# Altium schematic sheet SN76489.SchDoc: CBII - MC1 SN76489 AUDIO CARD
size A2; Engineer: SRKH; DocumentNumber: 1; Revision: 1.02; SheetNumber: 1; SheetTotal: 1
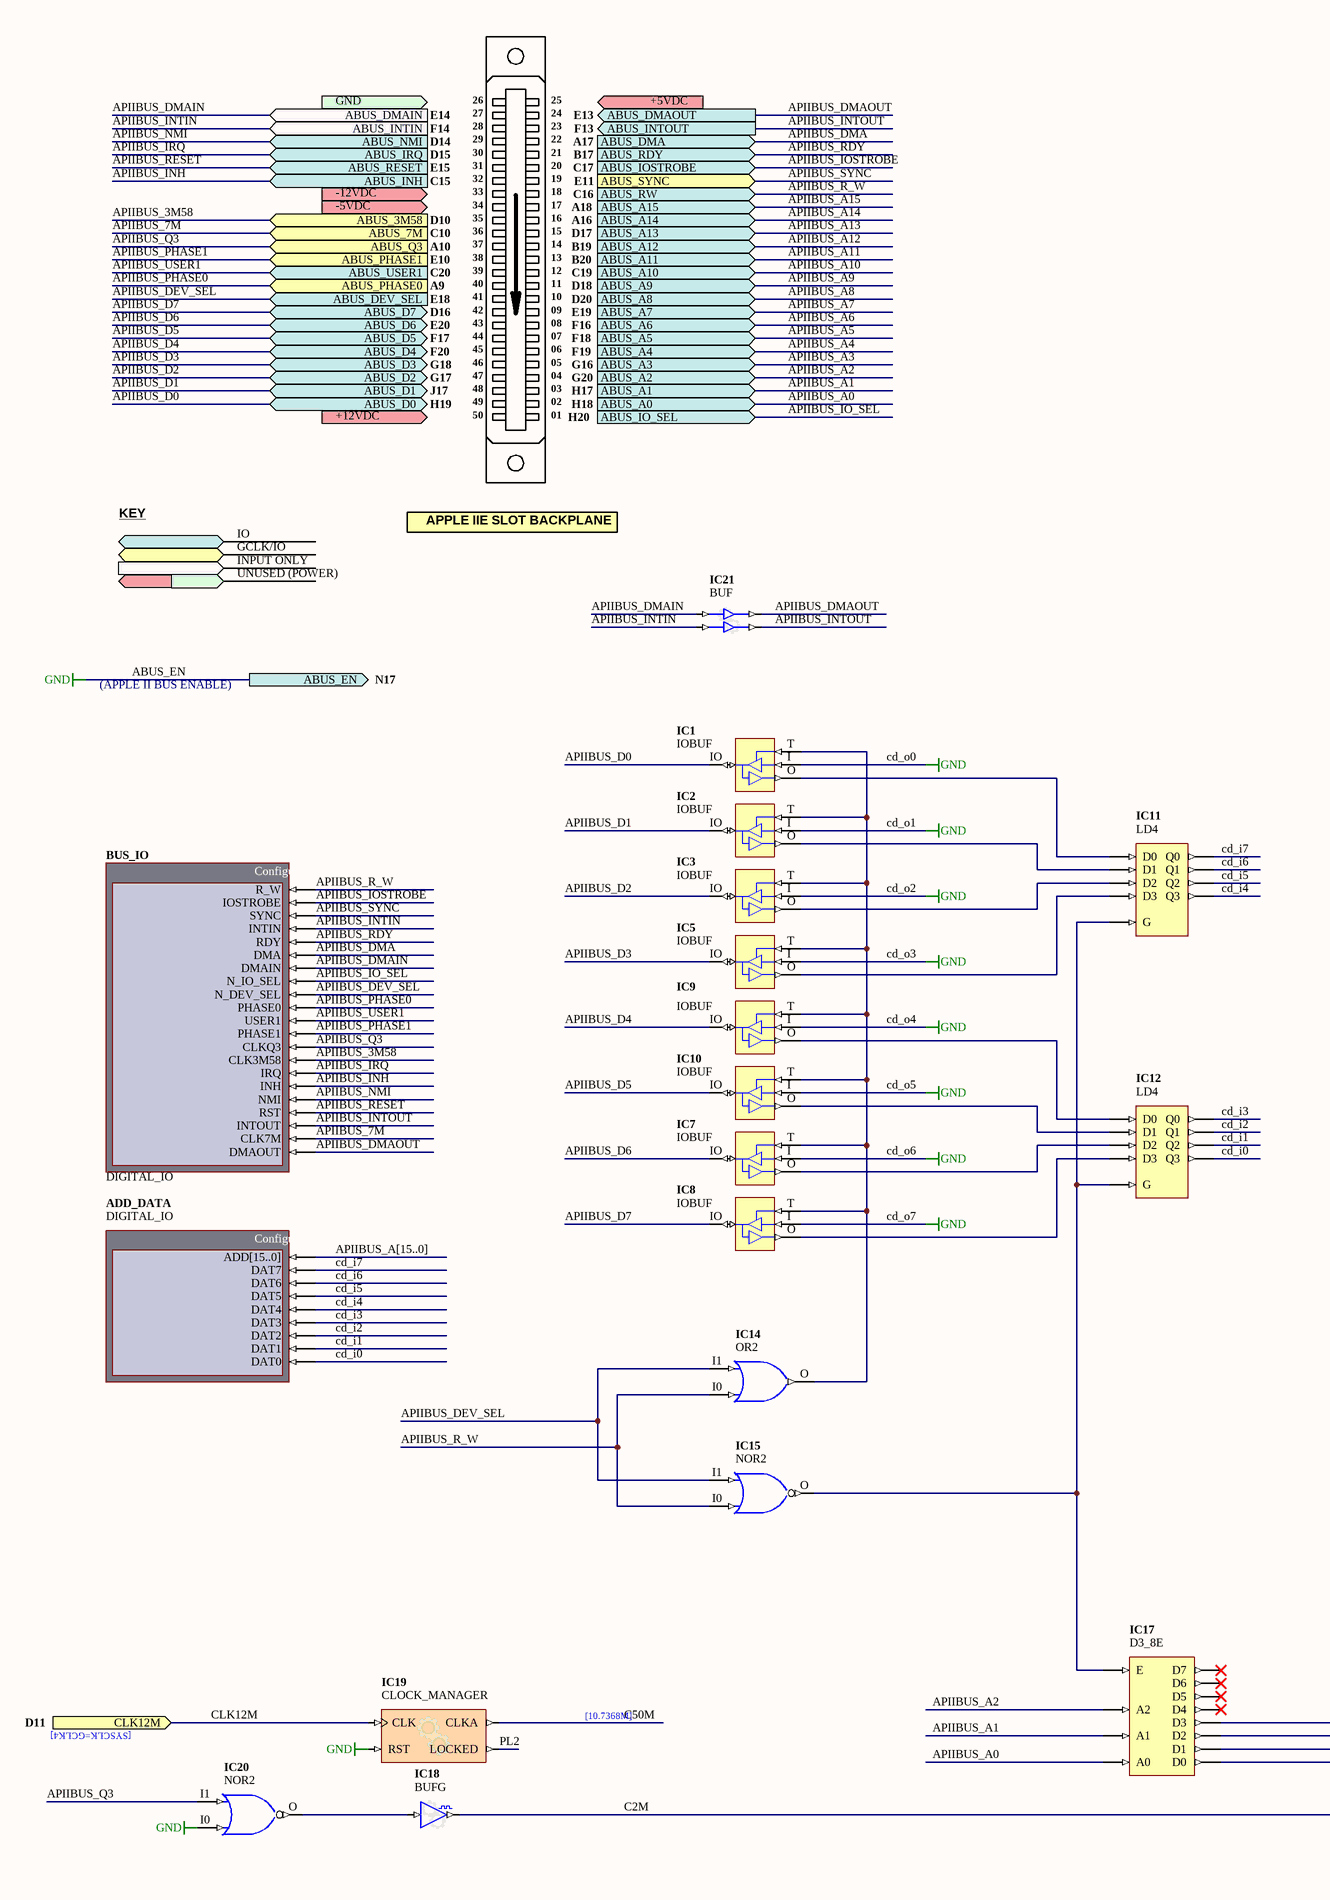
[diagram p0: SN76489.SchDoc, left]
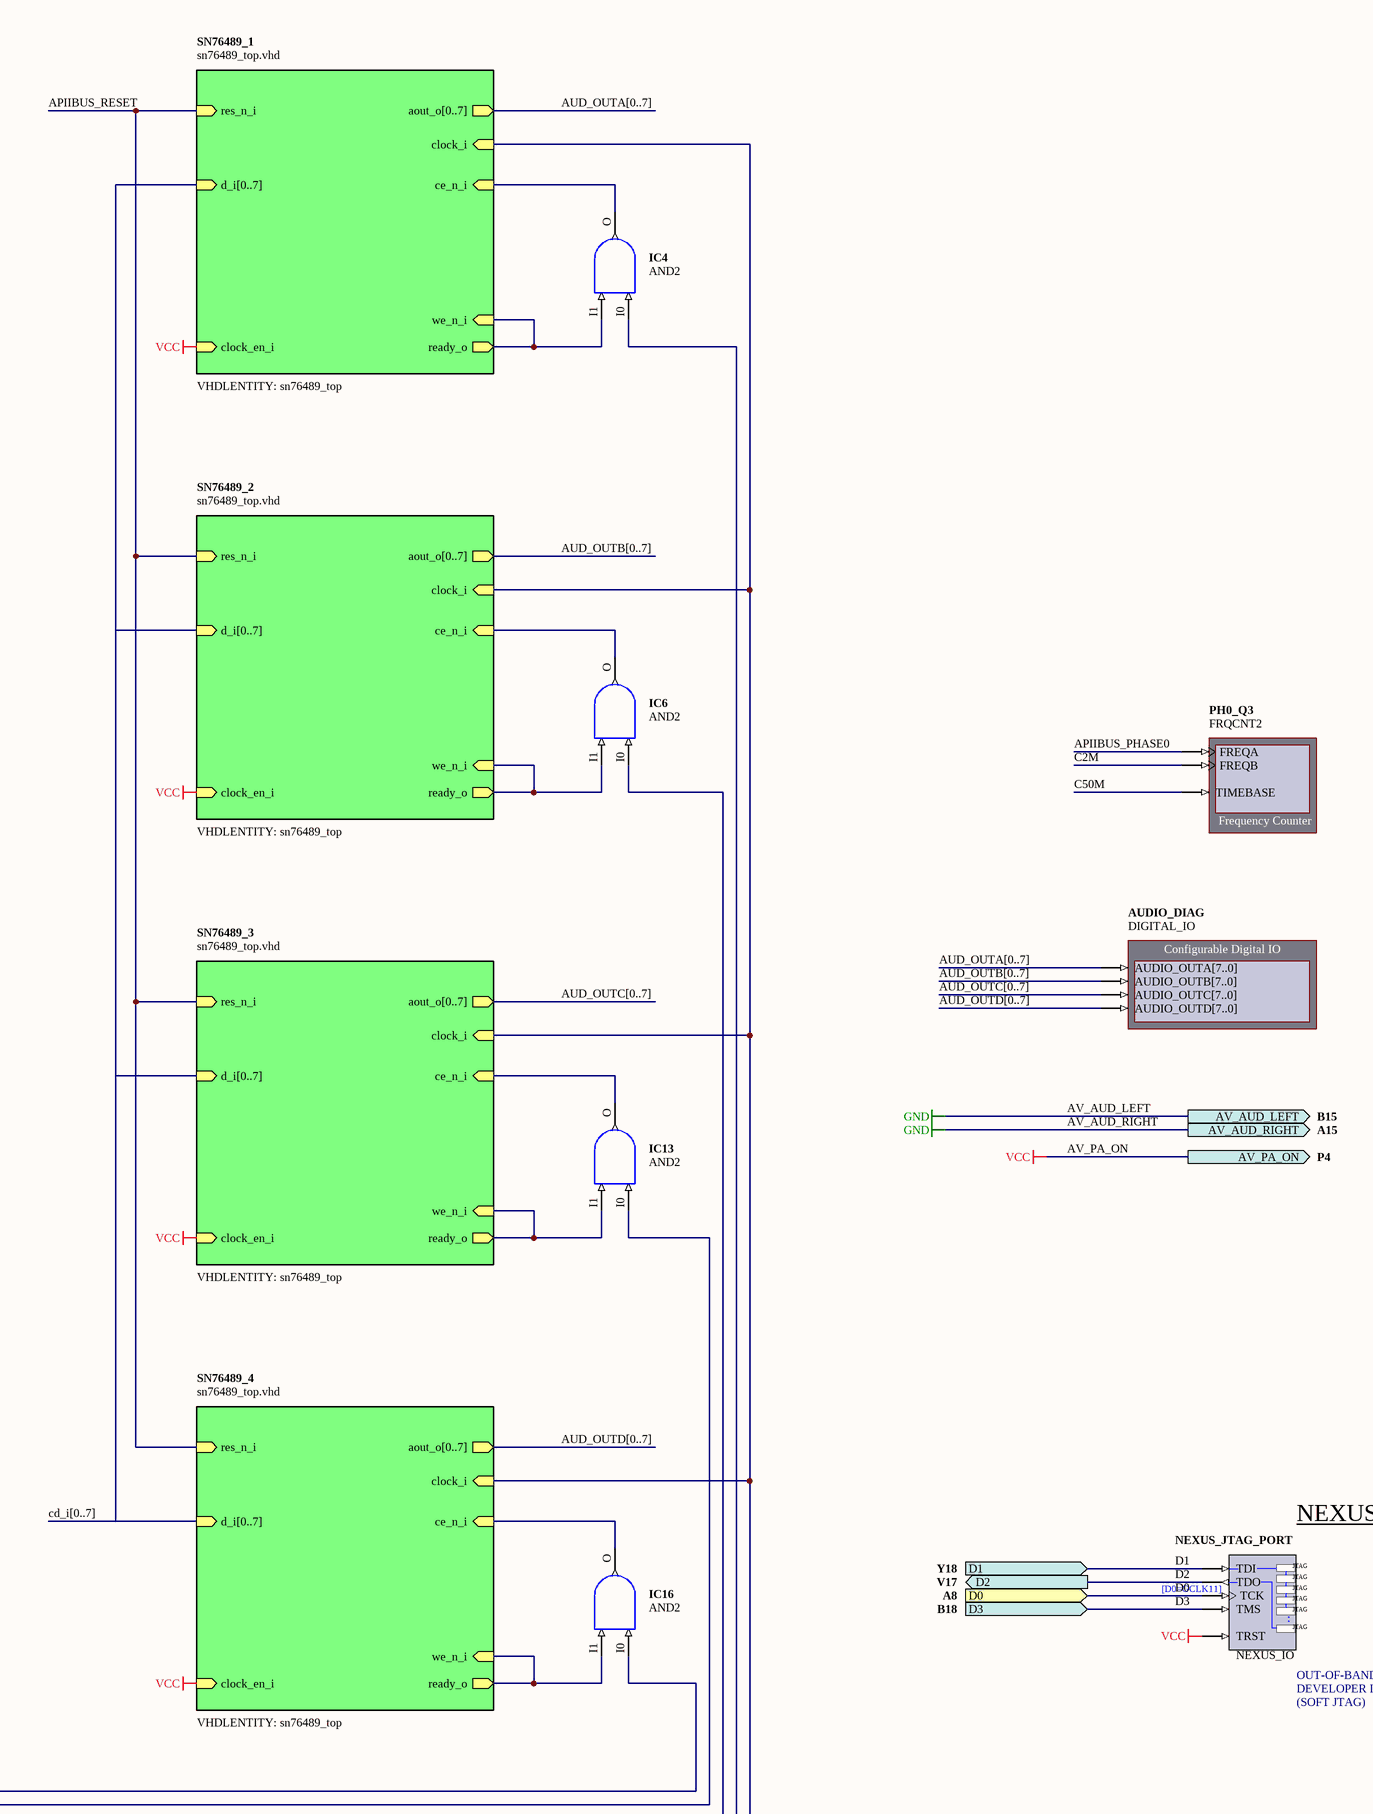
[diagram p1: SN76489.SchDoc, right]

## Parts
ADD_DATA  DIGITAL_IO
AUDIO_DIAG  DIGITAL_IO
BUS_IO  DIGITAL_IO
IC1  IOBUF
IC2  IOBUF
IC3  IOBUF
IC4  AND2
IC5  IOBUF
IC6  AND2
IC7  IOBUF
IC8  IOBUF
IC9  IOBUF
IC10  IOBUF
IC11  LD4
IC12  LD4
IC13  AND2
IC14  OR2
IC15  NOR2
IC16  AND2
IC17  D3_8E
IC18  BUFG
IC19  CLOCK_MANAGER
IC20  NOR2
IC21  BUF
NEXUS_JTAG_PORT  NEXUS_IO
PH0_Q3  FRQCNT2

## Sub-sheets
SN76489_1 = sn76489_top.vhd: ce_n_i (in), clock_en_i (in), clock_i (in), d_i[0..7] (in), ready_o (out), res_n_i (in), we_n_i (in), aout_o[0..7] (out)  | VHDLENTITY: sn76489_top
SN76489_2 = sn76489_top.vhd: ce_n_i (in), clock_en_i (in), clock_i (in), d_i[0..7] (in), ready_o (out), res_n_i (in), we_n_i (in), aout_o[0..7] (out)  | VHDLENTITY: sn76489_top
SN76489_3 = sn76489_top.vhd: ce_n_i (in), clock_en_i (in), clock_i (in), d_i[0..7] (in), ready_o (out), res_n_i (in), we_n_i (in), aout_o[0..7] (out)  | VHDLENTITY: sn76489_top
SN76489_4 = sn76489_top.vhd: ce_n_i (in), clock_en_i (in), clock_i (in), d_i[0..7] (in), ready_o (out), res_n_i (in), we_n_i (in), aout_o[0..7] (out)  | VHDLENTITY: sn76489_top

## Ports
ABUS_3M58 (in, see D10), ABUS_7M (in, see C10), ABUS_A0 (in, see H18), ABUS_A1 (in, see H17), ABUS_A2 (in, see G20), ABUS_A3 (in, see G16), ABUS_A4 (in, see F19), ABUS_A5 (in, see F18), ABUS_A6 (in, see F16), ABUS_A7 (in, see E19), ABUS_A8 (in, see D20), ABUS_A9 (in, see D18), ABUS_A10 (in, see C19), ABUS_A11 (in, see B20), ABUS_A12 (in, see B19), ABUS_A13 (in, see D17), ABUS_A14 (in, see A16), ABUS_A15 (in, see A18), ABUS_D0 (bidir, see H19), ABUS_D1 (bidir, see J17), ABUS_D2 (bidir, see G17), ABUS_D3 (bidir, see G18), ABUS_D4 (bidir, see F20), ABUS_D5 (bidir, see F17), ABUS_D6 (bidir, see E20), ABUS_D7 (bidir, see D16), ABUS_DEV_SEL (in, see E18), ABUS_DMA (in, see A17), ABUS_DMAIN (in, see E14), ABUS_DMAOUT (out, see E13), ABUS_EN (out, see N17), ABUS_INH (in, see C15), ABUS_INTIN (in, see F14), ABUS_INTOUT (out, see F13), ABUS_IO_SEL (in, see H20), ABUS_IOSTROBE (in, see C17), ABUS_IRQ (in, see D15), ABUS_NMI (in, see D14), ABUS_PHASE0 (in, see A9), ABUS_PHASE1 (in, see E10), ABUS_Q3 (in, see A10), ABUS_RDY (in, see B17), ABUS_RESET (in, see E15), ABUS_RW (in, see C16), ABUS_SYNC (in, see E11), ABUS_USER1 (in, see C20), AV_AUD_LEFT (out, see B15), AV_AUD_RIGHT (out, see A15), AV_PA_ON (out, see P4), CLK12M (in, see D11), D0 (in, see A8), D1 (in, see Y18), D2 (out, see V17), D3 (in, see B18)

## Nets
ABUS_EN: IC1.I IC2.I IC3.I IC5.I IC7.I IC8.I IC9.I IC10.I IC19.RST IC20.I0 ; port ABUS_EN, port AV_AUD_LEFT, port AV_AUD_RIGHT  [also labelled AV_AUD_LEFT, AV_AUD_RIGHT, cd_o0, cd_o1, cd_o2, cd_o3, cd_o4, cd_o5, cd_o6, cd_o7, GND]
AV_PA_ON: NEXUS_JTAG_PORT.TRST ; port AV_PA_ON, sheet SN76489_1/clock_en_i, sheet SN76489_2/clock_en_i, sheet SN76489_3/clock_en_i, sheet SN76489_4/clock_en_i  [also labelled VCC]
APIIBUS_3M58: BUS_IO.CLK3M58 ; port ABUS_3M58
APIIBUS_7M: BUS_IO.CLK7M ; port ABUS_7M
APIIBUS_A0: IC17.A0 ; port ABUS_A0
APIIBUS_A1: IC17.A1 ; port ABUS_A1
APIIBUS_A2: IC17.A2 ; port ABUS_A2
APIIBUS_D0: IC1.IO ; port ABUS_D0
APIIBUS_D1: IC2.IO ; port ABUS_D1
APIIBUS_D2: IC3.IO ; port ABUS_D2
APIIBUS_D3: IC5.IO ; port ABUS_D3
APIIBUS_D4: IC9.IO ; port ABUS_D4
APIIBUS_D5: IC10.IO ; port ABUS_D5
APIIBUS_D6: IC7.IO ; port ABUS_D6
APIIBUS_D7: IC8.IO ; port ABUS_D7
APIIBUS_DEV_SEL: BUS_IO.N_DEV_SEL IC14.I1 IC15.I1 ; port ABUS_DEV_SEL
APIIBUS_DMA: BUS_IO.DMA ; port ABUS_DMA
APIIBUS_DMAIN: BUS_IO.DMAIN IC21.I0 ; port ABUS_DMAIN
APIIBUS_DMAOUT: BUS_IO.DMAOUT IC21.O0 ; port ABUS_DMAOUT
APIIBUS_INH: BUS_IO.INH ; port ABUS_INH
APIIBUS_INTIN: BUS_IO.INTIN IC21.I1 ; port ABUS_INTIN
APIIBUS_INTOUT: BUS_IO.INTOUT IC21.O1 ; port ABUS_INTOUT
APIIBUS_IO_SEL: BUS_IO.N_IO_SEL ; port ABUS_IO_SEL
APIIBUS_IOSTROBE: BUS_IO.IOSTROBE ; port ABUS_IOSTROBE
APIIBUS_IRQ: BUS_IO.IRQ ; port ABUS_IRQ
APIIBUS_NMI: BUS_IO.NMI ; port ABUS_NMI
APIIBUS_PHASE0: BUS_IO.PHASE0 PH0_Q3.FREQA ; port ABUS_PHASE0
APIIBUS_PHASE1: BUS_IO.PHASE1 ; port ABUS_PHASE1
APIIBUS_Q3: BUS_IO.CLKQ3 IC20.I1 ; port ABUS_Q3
APIIBUS_R_W: BUS_IO.R_W IC14.I0 IC15.I0 ; port ABUS_RW
APIIBUS_RDY: BUS_IO.RDY ; port ABUS_RDY
APIIBUS_RESET: BUS_IO.RST ; port ABUS_RESET, sheet SN76489_1/res_n_i, sheet SN76489_2/res_n_i, sheet SN76489_3/res_n_i, sheet SN76489_4/res_n_i
APIIBUS_SYNC: BUS_IO.SYNC ; port ABUS_SYNC
APIIBUS_USER1: BUS_IO.USER1 ; port ABUS_USER1
C2M: IC18.O PH0_Q3.FREQB ; sheet SN76489_1/clock_i, sheet SN76489_2/clock_i, sheet SN76489_3/clock_i, sheet SN76489_4/clock_i
C50M: IC19.CLKA PH0_Q3.TIMEBASE
cd_i0: ADD_DATA.DAT0 IC12.Q3
cd_i1: ADD_DATA.DAT1 IC12.Q2
cd_i2: ADD_DATA.DAT2 IC12.Q1
cd_i3: ADD_DATA.DAT3 IC12.Q0
cd_i4: ADD_DATA.DAT4 IC11.Q3
cd_i5: ADD_DATA.DAT5 IC11.Q2
cd_i6: ADD_DATA.DAT6 IC11.Q1
cd_i7: ADD_DATA.DAT7 IC11.Q0
CLK12M: IC19.CLK ; port CLK12M
D0: NEXUS_JTAG_PORT.TCK ; port D0
D1: NEXUS_JTAG_PORT.TDI ; port D1
D2: NEXUS_JTAG_PORT.TDO ; port D2
D3: NEXUS_JTAG_PORT.TMS ; port D3
PL2: IC19.LOCKED
NetIC1_O: IC1.O IC11.D0
NetIC1_T: IC1.T IC2.T IC3.T IC5.T IC7.T IC8.T IC9.T IC10.T IC14.O
NetIC2_O: IC2.O IC11.D1
NetIC3_O: IC3.O IC11.D2
NetIC4_I0: IC4.I0 IC17.D0
NetIC4_I1: IC4.I1 ; sheet SN76489_1/ready_o, sheet SN76489_1/we_n_i
NetIC4_O: IC4.O ; sheet SN76489_1/ce_n_i
NetIC5_O: IC5.O IC11.D3
NetIC6_I0: IC6.I0 IC17.D1
NetIC6_I1: IC6.I1 ; sheet SN76489_2/ready_o, sheet SN76489_2/we_n_i
NetIC6_O: IC6.O ; sheet SN76489_2/ce_n_i
NetIC7_O: IC7.O IC12.D2
NetIC8_O: IC8.O IC12.D3
NetIC9_O: IC9.O IC12.D0
NetIC10_O: IC10.O IC12.D1
NetIC11_G: IC11.G IC12.G IC15.O IC17.E
NetIC13_I0: IC13.I0 IC17.D2
NetIC13_I1: IC13.I1 ; sheet SN76489_3/ready_o, sheet SN76489_3/we_n_i
NetIC13_O: IC13.O ; sheet SN76489_3/ce_n_i
NetIC16_I0: IC16.I0 IC17.D3
NetIC16_I1: IC16.I1 ; sheet SN76489_4/ready_o, sheet SN76489_4/we_n_i
NetIC16_O: IC16.O ; sheet SN76489_4/ce_n_i
NetIC18_I: IC18.I IC20.O

Not connected (* = marked no-connect by the designer): ADD_DATA ADD[15..0]; AUDIO_DIAG AUDIO_OUTA[7..0] AUDIO_OUTB[7..0] AUDIO_OUTC[7..0] AUDIO_OUTD[7..0]; IC17 D4* D5* D6* D7*

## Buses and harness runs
bus APIIBUS_A[15..0]
bus AUD_OUTA[0..7]
bus AUD_OUTA[0..7] = sheet SN76489_1/aout_o[0..7]
bus AUD_OUTB[0..7]
bus AUD_OUTB[0..7] = sheet SN76489_2/aout_o[0..7]
bus AUD_OUTC[0..7]
bus AUD_OUTC[0..7] = sheet SN76489_3/aout_o[0..7]
bus AUD_OUTD[0..7]
bus AUD_OUTD[0..7] = sheet SN76489_4/aout_o[0..7]
bus cd_i[0..7] = sheet SN76489_1/d_i[0..7] = sheet SN76489_2/d_i[0..7] = sheet SN76489_3/d_i[0..7] = sheet SN76489_4/d_i[0..7]

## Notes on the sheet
- GND
- 26
- 27
- 25
- 24
- +5VDC
- 28
- 29
- 30
- 31
- 32
- 23
- 22
- 21
- 20
- 19
- -12VDC
- -5VDC
- 33
- 34
- 35
- 36
- 37
- 18
- 17
- 16
- 15
- 14
- 38
- 39
- 40
- 41
- 42
- 13
- 12
- 11
- 10
- 09
- 43
- 44
- 45
- 46
- 47
- 08
- 07
- 06
- 05
- 04
- +12VDC
- 48
- 49
- 50
- 03
- 02
- 01
- KEY
- IO
- GCLK/IO
- INPUT ONLY
- UNUSED (POWER)
- APPLE IIE SLOT BACKPLANE
- (APPLE II BUS ENABLE)
- (near NEXUS_JTAG_PORT) NEXUS
- [D0=GCLK11]
- (near NEXUS_JTAG_PORT) OUT-OF-BAND
- (near NEXUS_JTAG_PORT) DEVELOPER INTERFACE
- (SOFT JTAG)
- [SYSCLK=GCLK4]
- (near IC19) [10.7368M]

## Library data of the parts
ADD_DATA = DIGITAL_IO: Configurable Digital IO; NEXUS_CORE: Instrument; NEXUS_JTAG_DEVICE: True; NEXUS_JTAG_ORDER: 0; ConfigurationParameters: {}Version[2.0]{}StorageType[3]{}InterfaceType[Parallel]{}SchCompWidth[140]{}Input0Name[ADD{1}15..0{2}]{}Input0Width[16]{}Input0InitValue[0]{}Input0Kind[Numeric]{}Input0NumRadix[Decimal]{}Input1Name[DAT7]{}Input1Width[1]{}Input1InitValue[0]{}Input1Kind[Numeric]{}Input1NumRadix[Decimal]{}Input2Name[DAT6]{}Input2Width[1]{}Input2InitValue[0]{}Input2Kind[Numeric]{}Input2NumRadix[Decimal]{}Input3Name[DAT5]{}Input3Width[1]{}Input3InitValue[0]{}Input3Kind[Numeric]{}Input3NumRadix[Decimal]{}Input4Name[DAT4]{}Input4Width[1]{}Input4InitValue[0]{}Input4Kind[Numeric]{}Input4NumRadix[Decimal]{}Input5Name[DAT3]{}Input5Width[1]{}Input5InitValue[0]{}Input5Kind[Numeric]{}Input5NumRadix[Decimal]{}Input6Name[DAT2]{}Input6Width[1]{}Input6InitValue[0]{}Input6Kind[Numeric]{}Input6NumRadix[Decimal]{}Input7Name[DAT1]{}Input7Width[1]{}Input7InitValue[0]{}Input7Kind[Numeric]{}Input7NumRadix[Decimal]{}Input8Name[DAT0]{}Input8Width[1]{}Input8InitValue[0]{}Input8Kind[Numeric]{}Input8NumRadix[Decimal]{}NoOutputs[ ]{}Designator[ADD_DATA]{}InternalID[0]{}
AUDIO_DIAG = DIGITAL_IO: Configurable Digital IO; NEXUS_CORE: Instrument; NEXUS_JTAG_DEVICE: True; NEXUS_JTAG_ORDER: 0; ConfigurationParameters: {}Version[2.0]{}StorageType[3]{}InterfaceType[Parallel]{}SchCompWidth[140]{}Input0Name[AUDIO_OUTA{1}7..0{2}]{}Input0Width[8]{}Input0InitValue[0]{}Input0Kind[Numeric]{}Input0NumRadix[Hexadecimal]{}Input1Name[AUDIO_OUTB{1}7..0{2}]{}Input1Width[8]{}Input1InitValue[0]{}Input1Kind[Numeric]{}Input1NumRadix[Hexadecimal]{}Input2Name[AUDIO_OUTC{1}7..0{2}]{}Input2Width[8]{}Input2InitValue[0]{}Input2Kind[Numeric]{}Input2NumRadix[Hexadecimal]{}Input3Name[AUDIO_OUTD{1}7..0{2}]{}Input3Width[8]{}Input3InitValue[0]{}Input3Kind[LEDs]{}Input3LEDStyle[Red]{}NoOutputs[ ]{}Designator[AUDIO_DIAG]{}InternalID[1]{}
BUS_IO = DIGITAL_IO: Configurable Digital IO; NEXUS_CORE: Instrument; NEXUS_JTAG_DEVICE: True; NEXUS_JTAG_ORDER: 0; ConfigurationParameters: {}Version[2.0]{}StorageType[3]{}InterfaceType[Parallel]{}SchCompWidth[140]{}Input0Name[R_W]{}Input0Width[1]{}Input0InitValue[0]{}Input0Kind[LEDs]{}Input0LEDStyle[Red]{}Input1Name[IOSTROBE]{}Input1Width[1]{}Input1InitValue[0]{}Input1Kind[LEDs]{}Input1LEDStyle[White]{}Input2Name[SYNC]{}Input2Width[1]{}Input2InitValue[0]{}Input2Kind[LEDs]{}Input2LEDStyle[Red]{}Input3Name[INTIN]{}Input3Width[1]{}Input3InitValue[0]{}Input3Kind[LEDs]{}Input3LEDStyle[Red]{}Input4Name[RDY]{}Input4Width[1]{}Input4InitValue[0]{}Input4Kind[LEDs]{}Input4LEDStyle[Red]{}Input5Name[DMA]{}Input5Width[1]{}Input5InitValue[0]{}Input5Kind[LEDs]{}Input5LEDStyle[Red]{}Input6Name[DMAIN]{}Input6Width[1]{}Input6InitValue[0]{}Input6Kind[LEDs]{}Input6LEDStyle[Red]{}Input7Name[N_IO_SEL]{}Input7Width[1]{}Input7InitValue[0]{}Input7Kind[LEDs]{}Input7LEDStyle[Green]{}Input8Name[N_DEV_SEL]{}Input8Width[1]{}Input8InitValue[0]{}Input8Kind[LEDs]{}Input8LEDStyle[Blue]{}Input9Name[PHASE0]{}Input9Width[1]{}Input9InitValue[0]{}Input9Kind[LEDs]{}Input9LEDStyle[Red]{}Input10Name[USER1]{}Input10Width[1]{}Input10InitValue[0]{}Input10Kind[LEDs]{}Input10LEDStyle[Red]{}Input11Name[PHASE1]{}Input11Width[1]{}Input11InitValue[0]{}Input11Kind[LEDs]{}Input11LEDStyle[Red]{}Input12Name[CLKQ3]{}Input12Width[1]{}Input12InitValue[0]{}Input12Kind[LEDs]{}Input12LEDStyle[Red]{}Input13Name[CLK3M58]{}Input13Width[1]{}Input13InitValue[0]{}Input13Kind[LEDs]{}Input13LEDStyle[Red]{}Input14Name[IRQ]{}Input14Width[1]{}Input14InitValue[0]{}Input14Kind[LEDs]{}Input14LEDStyle[Red]{}Input15Name[INH]{}Input15Width[1]{}Input15InitValue[0]{}Input15Kind[LEDs]{}Input15LEDStyle[Red]{}Input16Name[NMI]{}Input16Width[1]{}Input16InitValue[0]{}Input16Kind[LEDs]{}Input16LEDStyle[Red]{}Input17Name[RST]{}Input17Width[1]{}Input17InitValue[0]{}Input17Kind[LEDs]{}Input17LEDStyle[Red]{}Input18Name[INTOUT]{}Input18Width[1]{}Input18InitValue[0]{}Input18Kind[LEDs]{}Input18LEDStyle[Red]{}Input19Name[CLK7M]{}Input19Width[1]{}Input19InitValue[0]{}Input19Kind[LEDs]{}Input19LEDStyle[Red]{}Input20Name[DMAOUT]{}Input20Width[1]{}Input20InitValue[0]{}Input20Kind[LEDs]{}Input20LEDStyle[Red]{}NoOutputs[ ]{}Designator[BUS_IO]{}InternalID[2]{}
IC1-IC3 IC5 IC7-IC10 = IOBUF: Bi-Directional Buffer using the LVTTL standard; FPGAVendor: Xilinx
IC4 IC6 IC13 IC16 = AND2: 2-Input AND Gate; FPGAVendor: Xilinx
IC11 IC12 = LD4: Multiple Transparent Data Latches; FPGAVendor: Xilinx
IC14 = OR2: 2-Input OR Gate; FPGAVendor: Xilinx
IC15 IC20 = NOR2: 2-Input NOR Gate; FPGAVendor: Xilinx
IC17 = D3_8E: 3- to 8-Line Decoder/Demultiplexer with Enable; FPGAVendor: Xilinx
IC18 = BUFG: Configurable Global Clock Buffer; ConfiguratorName: GENERIC_BUFFER; ConfigurationParameters: {}Version[1.1]{}SignalCount[1]{}SignalWidth0[1]{}OutputOption0[Global Clock]{}EnableMode[None]{}ShowPinNames[False]{}
IC19 = CLOCKMANAGER: Configurable Clock Manager; ConfiguratorName: GENERIC_CLOCKMANAGER; ConfigurationParameters: {}Version[1.0]{}Option_Configuration[object _1: TClockManagerPersist / VersionMajor [ 0 / VersionMinor [ 0 / InputFreq [ 24.000000000000000000 / InputName [ 'CLK' / OutputTargets [ < / item / Name [ 'CLKA' / OutFreqMin [ 99.000000000000000000 / OutFreqMax [ 101.000000000000000000 / OutPostDivider [ 1.000000000000000000 / end> / OutputDevices [ < / item / Name [ 'Spartan3AN' / Valid [ True / OutputActuals [ < / item / Name [ 'CLK0' / Multipler [ 1.000000000000000000 / Divider [ 1.000000000000000000 / OutFreq [ 24.000000000000000000 / OutputMap [ 1 / end / item / Name [ 'CLK90' / Multipler [ 1.000000000000000000 / Divider [ 1.000000000000000000 / OutPhase [ 90.000000000000000000 / OutFreq [ 24.000000000000000000 / OutputMap [ 2 / end / item / Name [ 'CLK180' / Multipler [ 1.000000000000000000 / Divider [ 1.000000000000000000 / OutPhase [ 180.000000000000000000 / OutFreq [ 24.000000000000000000 / OutputMap [ 3 / end / item / Name [ 'CLK270' / Multipler [ 1.000000000000000000 / Divider [ 1.000000000000000000 / OutPhase [ 270.000000000000000000 / OutFreq [ 24.000000000000000000 / OutputMap [ 4 / end / item / Name [ 'CLK2X' / Multipler [ 2.000000000000000000 / Divider [ 1.000000000000000000 / OutFreq [ 48.000000000000000000 / OutputMap [ 5 / end / item / Name [ 'CLKDV' / Multipler [ 1.000000000000000000 / Divider [ 16.000000000000000000 / OutFreq [ 1.500000000000000000 / OutputMap [ 6 / end / item / Name [ 'CLK2X180' / Multipler [ 1.000000000000000000 / Divider [ 1.000000000000000000 / OutPhase [ 180.000000000000000000 / OutFreq [ 48.000000000000000000 / OutputMap [ 7 / end / item / Name [ 'CLKFX' / Multipler [ 25.000000000000000000 / Divider [ 6.000000000000000000 / OutFreq [ 100.000000000000000000 / OutputMap [ 0 / end / item / Name [ 'CLKFX180' / Multipler [ 1.000000000000000000 / Divider [ 1.000000000000000000 / OutPhase [ 180.000000000000000000 / OutFreq [ 100.000000000000000000 / OutputMap [ 8 / end> / InternalActuals [ <> / CustomVars [ <> / end> / MinInputFreq [ 1.000000000000000000 / MaxInputFreq [ 280.000000000000000000 / MinOutputFreq [ 18.000000000000000000 / MaxOutputFreq [ 210.000000000000000000 / MaxOutputCount [ 9 / end]{}
IC21 = BUF: Configurable Buffer; ConfiguratorName: GENERIC_BUFFER; ConfigurationParameters: {}Version[1.1]{}SignalCount[2]{}SignalWidth0[1]{}OutputOption0[Normal]{}SignalWidth1[1]{}OutputOption1[Normal]{}EnableMode[None]{}ShowPinNames[False]{}
NEXUS_JTAG_PORT = NEXUS_JTAG_PORT: Soft Nexus-Chain Connector; NEXUS_JTAG_CONNECTOR: True
PH0_Q3 = FRQCNT2: Frequency Counter; NEXUS_CORE: Instrument; NEXUS_JTAG_DEVICE: True; NEXUS_JTAG_ORDER: 0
